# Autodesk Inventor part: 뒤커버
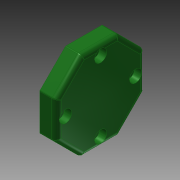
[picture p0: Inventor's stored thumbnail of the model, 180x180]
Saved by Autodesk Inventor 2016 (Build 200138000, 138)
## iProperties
Created: 2015-11
Part Number: 뒤커버
Material: 알루미늄 6061
Document SubType Name: Modeling
Designer: mduedu
Density: 1 g/cm^3
Appearance: 매끄러움 - 짙은 산림 녹색
Author: mduedu
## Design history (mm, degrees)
sketch "스케치5" dims "d66" = 58
  geometry: L1 (12.012, 29)-(29, 12.012); L2 (29, 12.012)-(29, -12.012); L3 (29, -12.012)-(12.012, -29); L4 (12.012, -29)-(-12.012, -29); L5 (-12.012, -29)-(-29, -12.012); L6 (-29, -12.012)-(-29, 12.012); L7 (-29, 12.012)-(-12.012, 29); L8 (-12.012, 29)-(12.012, 29); 4 further points
  constraints: 16 end point, 2 coincident, 2 vertical alignment, 1 midpoint, 19 other
extrude "돌출2" new body sketch "스케치5" distance "d67" = 11; taper "d68" = 0 deg
sketch "스케치6"
  geometry: C1 r 16 at (0, 0); 1 further point
  constraints: 1 centre point, 1 coincident
  dimensions: "d69" = 32 diameter of C1
extrude "돌출3" join sketch "스케치6" distance "d70" = 3; taper "d71" = 0 deg
hole "구멍5" diameter "d74" = 28; stored, may be unused: countersink angle "d78" = 90 deg, drill point angle "d80" = 0 deg; dims "d75" = 6, "d76" = 4, "d77" = 2, "d79" = 10, "d98" = 10, "d99" = 10
fillet "모깎기7" dims "d81" = 1
fillet "모깎기8" dims "d82" = 3
fillet "모깎기9" dims "d83" = 3
fillet "모깎기10" dims "d84" = 0.3
sketch "스케치7" dims "d85" = 46
  geometry: 3 further points
  constraints: 2 vertical alignment, 1 coincident, 2 other
hole "구멍6" sketch "스케치7" at (0, 23) diameter "d86" = 4.5; stored, may be unused: countersink angle "d90" = 90 deg, drill point angle "d92" = 0 deg; dims "d87" = 6, "d88" = 8, "d89" = 4.6, "d91" = 10
node "솔리드2"
pattern_circular "원형 패턴3" dims angle "d94" = 360 deg
